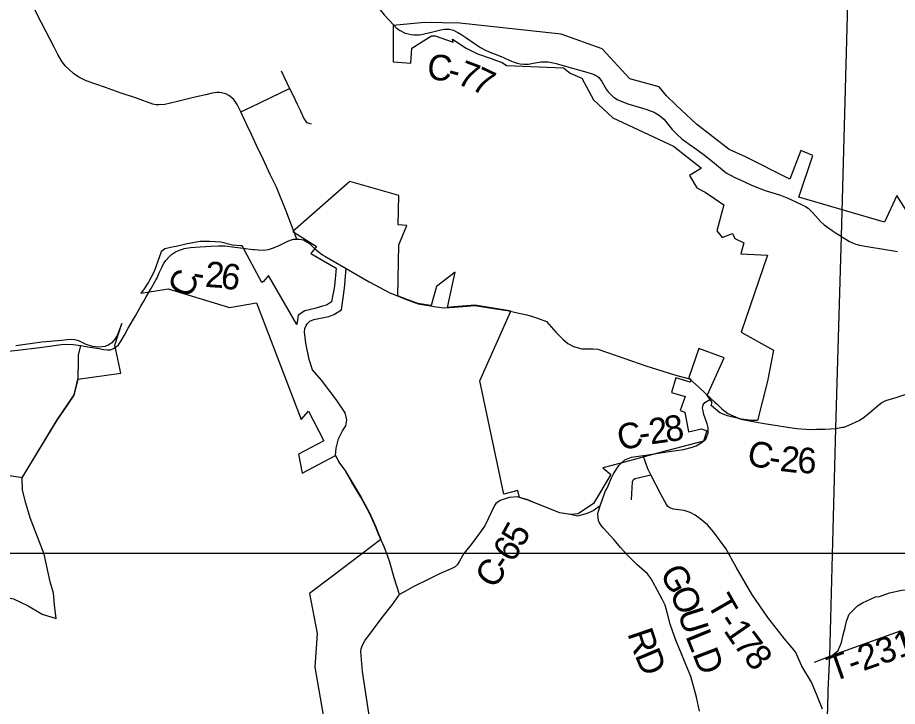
# Model space of a CAD drawing. Extents: x 2402298 to 2498138, y 789485 to 950881.
# Drawn here: x 2476688 to 2487007, y 857480 to 865555 of the extents above; entities that cross this region are included whole.
import ezdxf

# ---------------------------------------------------------------- set-up
doc = ezdxf.new("R2010")
doc.units = 0
for name, color, linetype in [('GM_X_City_Street', 7, 'Continuous'), ('GM_X_Corporation', 7, 'Continuous'), ('GM_X_County_Road', 7, 'Continuous'), ('GM_X_County_Road_Text', 7, 'Continuous'), ('GM_X_Township', 7, 'Continuous'), ('GM_X_Township_Road', 7, 'Continuous'), ('GM_X_Township_Road_Text', 7, 'Continuous'), ('SH_Text', 7, 'Continuous')]:
    doc.layers.add(name, color=color, linetype=linetype)

msp = doc.modelspace()

# ---------------------------------------------------------------- linework, layer by layer
at = {"layer": 'GM_X_City_Street'}
for points in [[(2479778, 864930), (2479879, 864725), (2479920, 864642), (2479968, 864542), (2480003, 864469), (2480011, 864451)], [(2479306, 864450), (2479433, 864509), (2479879, 864725)], [(2480011, 864451), (2480047, 864371), (2480059, 864350), (2480076, 864327), (2480132, 864309)]]:
    msp.add_lwpolyline(points, dxfattribs=at)
at = {"layer": 'GM_X_Corporation'}
for points in [[(2487193, 863169), (2487001, 863468), (2486857, 863158), (2485849, 863449), (2486015, 863937), (2485875, 863997), (2485747, 863661), (2485225, 863921), (2485034, 864008), (2484649, 864305), (2484413, 864530), (2484300, 864639), (2484214, 864743), (2483869, 864837), (2483546, 865190), (2483065, 865362), (2481873, 865488), (2481459, 865498), (2481091, 865464), (2481093, 865038), (2481299, 865020), (2481312, 865197), (2481543, 865342), (2481587, 865343), (2481795, 865267), (2481789, 865302), (2481949, 865198), (2482076, 865133), (2482083, 865132), (2482255, 865072), (2482282, 865059), (2482371, 865028), (2482423, 864992), (2483091, 864968), (2483169, 864902), (2483307, 864844), (2483441, 864590), (2483668, 864379), (2484379, 864047), (2484708, 863790), (2484570, 863704), (2484656, 863561), (2484752, 863508), (2484972, 863359), (2484890, 863055), (2484951, 862978), (2485073, 863025), (2485099, 862967), (2485205, 862913), (2485170, 862785), (2485485, 862768), (2485173, 861866), (2485554, 861655), (2485483, 861292), (2485368, 860830), (2485300, 860833), (2485174, 860846), (2485014, 860888), (2484924, 860920), (2484822, 861006), (2484836, 861045), (2484777, 861126), (2484974, 861566), (2484677, 861675), (2484560, 861334), (2484584, 861313), (2484575, 861282), (2484409, 861333), (2484359, 861160), (2484517, 861112), (2484461, 860948), (2484512, 860929), (2484557, 860700), (2484709, 860732), (2484772, 860709), (2484731, 860591), (2484224, 860455), (2483763, 860332), (2483552, 860276), (2483646, 860199), (2483443, 859859), (2483263, 859736), (2483171, 859730), (2483047, 859750), (2482764, 859861), (2482671, 859900), (2482573, 859929), (2482556, 860010), (2482391, 859966), (2482109, 861297), (2482473, 862114), (2482433, 862123), (2482051, 862183), (2481955, 862175), (2481810, 862164), (2481730, 862157), (2481820, 862569), (2481600, 862404), (2481540, 862179), (2481530, 862180), (2481384, 862203), (2481235, 862257), (2481147, 862294), (2481158, 862890), (2481254, 863117), (2481153, 863124), (2481159, 863468), (2480586, 863635), (2479916, 863049), (2480192, 862870), (2480128, 862789), (2480425, 862617), (2480403, 862407), (2480369, 862224), (2480311, 862185), (2480265, 862171), (2480174, 862144), (2480055, 862117), (2479977, 862067), (2479965, 861957), (2479630, 862532), (2479574, 862461), (2479553, 862450), (2479323, 862878), (2479306, 862878), (2479210, 862887), (2479073, 862922), (2478939, 862930), (2478831, 862929), (2478678, 862901), (2478546, 862873), (2478519, 862867), (2478414, 862845), (2478372, 862808), (2478288, 862578), (2478222, 862455), (2478163, 862364), (2478133, 862325), (2478211, 862338), (2478453, 862376), (2479175, 862155), (2479490, 862210), (2480015, 860842), (2480101, 860942), (2480278, 860595), (2479981, 860438), (2480024, 860213), (2480417, 860422), (2480465, 860333), (2480528, 860251), (2480607, 860112), (2480713, 859935), (2480816, 859748), (2480885, 859593), (2480920, 859503), (2480950, 859437), (2480380, 859007), (2480111, 858805), (2480202, 858336), (2480174, 857941), (2480300, 857222)], [(2475627, 860345), (2476742, 860163), (2476765, 860200), (2477152, 860839), (2477351, 861132), (2477396, 861315), (2477898, 861387), (2477828, 861716), (2477910, 861968), (2477854, 861829), (2477828, 861785), (2477795, 861744), (2477758, 861719), (2477715, 861701), (2477639, 861693), (2477565, 861700), (2477493, 861723), (2477407, 861764), (2477356, 861777), (2477303, 861781), (2477201, 861771), (2476971, 861751), (2476668, 861707)]]:
    msp.add_lwpolyline(points, dxfattribs=at)
at = {"layer": 'GM_X_County_Road'}
msp.add_line((2480293, 862757), (2480542, 862614), dxfattribs=at)
for points in [[(2480269, 866045), (2480346, 866031), (2480430, 866017), (2480513, 866001), (2480583, 865985), (2480637, 865965), (2480682, 865942), (2480721, 865918), (2480762, 865883), (2480794, 865845), (2480924, 865666), (2480988, 865587), (2481100, 865465), (2481132, 865433), (2481174, 865403), (2481217, 865381)], [(2479963, 862959), (2479838, 863286), (2479723, 863569), (2479652, 863717), (2479568, 863897), (2479491, 864057), (2479432, 864185), (2479377, 864299), (2479325, 864407), (2479306, 864450), (2479272, 864519), (2479257, 864547), (2479238, 864573), (2479223, 864594), (2479201, 864616), (2479165, 864641), (2479129, 864660), (2479081, 864674), (2479054, 864678), (2479023, 864677), (2478970, 864669), (2478911, 864655), (2478751, 864617), (2478548, 864568), (2478414, 864535), (2478349, 864531), (2478313, 864534), (2478273, 864542), (2478081, 864609), (2477890, 864674), (2477717, 864734), (2477492, 864815), (2477406, 864858), (2477344, 864901), (2477244, 864990), (2477202, 865049), (2477158, 865122), (2477116, 865208), (2476967, 865494), (2476851, 865723)], [(2481217, 865381), (2481221, 865378), (2481267, 865363), (2481306, 865356), (2481337, 865353), (2481369, 865353), (2481400, 865354), (2481426, 865358), (2481473, 865367), (2481528, 865381), (2481653, 865411), (2481691, 865418), (2481729, 865420), (2481755, 865418), (2481780, 865413), (2481802, 865406), (2481828, 865394), (2481853, 865381), (2481898, 865353), (2481946, 865321), (2482060, 865245), (2482119, 865206), (2482167, 865177), (2482226, 865149), (2482289, 865125), (2482340, 865106), (2482387, 865087), (2482455, 865055), (2482481, 865044)], [(2482481, 865044), (2482501, 865036), (2482546, 865022), (2482583, 865015), (2482624, 865011), (2482653, 865010), (2482681, 865011), (2482735, 865020), (2482783, 865029), (2482827, 865035), (2482880, 865037), (2482907, 865036), (2482930, 865032), (2482968, 865025), (2483003, 865017), (2483152, 864974), (2483268, 864942), (2483363, 864915), (2483427, 864896), (2483450, 864887), (2483470, 864877), (2483487, 864867), (2483504, 864854), (2483522, 864834), (2483541, 864807), (2483576, 864743), (2483593, 864716), (2483616, 864686), (2483643, 864656), (2483678, 864624), (2483693, 864613), (2483709, 864603), (2483728, 864592), (2483746, 864583), (2483794, 864562), (2483845, 864545), (2484019, 864492), (2484069, 864476), (2484119, 864459), (2484142, 864450), (2484166, 864439), (2484187, 864427), (2484206, 864415), (2484237, 864391), (2484266, 864365), (2484292, 864336), (2484320, 864301), (2484365, 864244), (2484391, 864214), (2484422, 864184), (2484478, 864134), (2484564, 864072), (2484653, 864008), (2484745, 863942), (2484859, 863854), (2484914, 863806), (2484946, 863778), (2484981, 863750), (2485012, 863729), (2485048, 863708), (2485099, 863681), (2485154, 863656), (2485297, 863592), (2485405, 863546), (2485455, 863528), (2485635, 863474), (2485714, 863441), (2485822, 863393), (2485897, 863358), (2485929, 863340), (2485959, 863320), (2486004, 863277), (2486046, 863231), (2486107, 863164), (2486147, 863127), (2486241, 863060), (2486300, 863021), (2486309, 863015), (2486348, 862991)], [(2486348, 862991), (2486352, 862988), (2486445, 862929), (2486480, 862913), (2486520, 862899), (2486562, 862888), (2486654, 862873), (2486845, 862842), (2486967, 862821), (2487008, 862811)], [(2479464, 862837), (2479510, 862832), (2479567, 862830), (2479632, 862837), (2479691, 862856), (2479762, 862886), (2479842, 862927), (2479886, 862945), (2479929, 862956), (2479963, 862959)], [(2479963, 862959), (2479994, 862958), (2480042, 862948), (2480078, 862927), (2480110, 862905), (2480172, 862849), (2480214, 862812), (2480264, 862774), (2480293, 862757)], [(2478323, 862506), (2478349, 862562), (2478378, 862625), (2478405, 862675), (2478432, 862712), (2478462, 862747), (2478495, 862778), (2478541, 862809), (2478587, 862830), (2478624, 862841)], [(2478624, 862841), (2478643, 862847), (2478716, 862858), (2478830, 862867), (2478954, 862877), (2479049, 862880), (2479118, 862878), (2479240, 862862), (2479332, 862851), (2479448, 862838), (2479464, 862837)], [(2480534, 860239), (2480529, 860248), (2480513, 860269), (2480466, 860330), (2480417, 860421), (2480426, 860508), (2480451, 860618), (2480499, 860709), (2480537, 860769), (2480548, 860838), (2480529, 860923), (2480423, 861076), (2480253, 861305), (2480147, 861426), (2480106, 861548), (2480070, 861739), (2480054, 861870), (2480057, 861912), (2480073, 861947), (2480089, 861970), (2480115, 861996), (2480162, 862017), (2480340, 862052), (2480398, 862075), (2480487, 862128), (2480523, 862382), (2480542, 862614)], [(2480542, 862614), (2480810, 862457), (2481055, 862330), (2481065, 862326), (2481192, 862272)], [(2478168, 862229), (2478193, 862273), (2478246, 862367), (2478312, 862483), (2478323, 862506)], [(2481192, 862272), (2481236, 862254), (2481385, 862200), (2481455, 862189), (2481531, 862177), (2481597, 862166)], [(2477905, 861772), (2477940, 861832), (2477983, 861913), (2478069, 862059), (2478134, 862172), (2478168, 862229)], [(2481597, 862166), (2481658, 862156), (2481689, 862151), (2481811, 862161), (2481910, 862169)], [(2481910, 862169), (2481956, 862173), (2482052, 862180), (2482373, 862130), (2482435, 862120), (2482532, 862098)], [(2482532, 862098), (2482661, 862069), (2482726, 862050), (2482785, 862033), (2482890, 861994), (2482999, 861869), (2483082, 861784), (2483142, 861736), (2483209, 861699), (2483307, 861670), (2483437, 861672), (2483495, 861669), (2483810, 861558), (2484057, 861471), (2484331, 861388), (2484447, 861351), (2484452, 861350), (2484496, 861338)], [(2476034, 861660), (2476039, 861659), (2476091, 861649), (2476176, 861635), (2476282, 861626), (2476385, 861627), (2476532, 861639), (2476654, 861653), (2476980, 861692), (2477200, 861722), (2477262, 861726), (2477340, 861721), (2477430, 861709), (2477490, 861700), (2477564, 861687), (2477643, 861674), (2477697, 861665), (2477741, 861661), (2477777, 861662), (2477812, 861676), (2477843, 861697), (2477870, 861719), (2477894, 861754), (2477905, 861772)], [(2484496, 861338), (2484570, 861319), (2484681, 861220), (2484822, 861086)], [(2486362, 860752), (2486381, 860755), (2486436, 860775), (2486559, 860831), (2486623, 860875), (2486665, 860909), (2486708, 860945), (2486791, 861014), (2486825, 861041), (2486855, 861060), (2486885, 861070), (2486979, 861098), (2487122, 861145), (2487343, 861226), (2487541, 861292), (2487648, 861333)], [(2484055, 860427), (2484225, 860453), (2484386, 860475), (2484498, 860493), (2484587, 860514), (2484647, 860536), (2484707, 860569), (2484761, 860614), (2484786, 860686), (2484787, 860746), (2484776, 860794), (2484751, 860858), (2484736, 860903), (2484728, 860945), (2484721, 860976), (2484727, 861017), (2484748, 861043), (2484822, 861086)], [(2484822, 861086), (2484865, 861048), (2484896, 861019)], [(2484896, 861019), (2484949, 860970), (2485019, 860915), (2485172, 860848), (2485314, 860821), (2485353, 860813)], [(2485353, 860813), (2485443, 860795), (2485573, 860776), (2485717, 860752), (2485827, 860736), (2485983, 860728), (2486059, 860729), (2486158, 860730), (2486284, 860739), (2486362, 860752)], [(2483679, 860208), (2483703, 860249), (2483739, 860303), (2483764, 860329), (2483812, 860370), (2483890, 860400), (2484025, 860423), (2484055, 860427)], [(2481014, 859281), (2481003, 859310), (2480989, 859349), (2480922, 859500), (2480886, 859590), (2480817, 859745), (2480715, 859932), (2480609, 860109), (2480534, 860239)], [(2483615, 860067), (2483651, 860151), (2483679, 860208)], [(2483522, 859831), (2483582, 860007), (2483603, 860039), (2483615, 860067)], [(2482692, 859890), (2482677, 859896), (2482632, 859910), (2482551, 859935), (2482454, 859927), (2482349, 859895), (2482299, 859860), (2482281, 859834), (2482169, 859598), (2482087, 859482), (2482007, 859376), (2481922, 859273), (2481889, 859217), (2481867, 859173), (2481842, 859138), (2481820, 859117), (2481774, 859092), (2481638, 859032), (2481510, 858972), (2481334, 858885), (2481166, 858792), (2481104, 858986), (2481053, 859169), (2481014, 859281)], [(2483189, 859724), (2483169, 859728), (2483118, 859737), (2483046, 859750), (2482832, 859834), (2482692, 859890)], [(2483522, 859831), (2483439, 859774), (2483358, 859739), (2483338, 859732)], [(2484687, 857422), (2484649, 857589), (2484583, 857830), (2484527, 857969), (2484467, 858115), (2484413, 858243), (2484368, 858364), (2484341, 858442), (2484308, 858580), (2484283, 858666), (2484249, 858736), (2484220, 858788), (2484195, 858840), (2484144, 858933), (2484111, 858986), (2484075, 859032), (2483952, 859145), (2483837, 859257), (2483761, 859344), (2483684, 859434), (2483637, 859484), (2483558, 859570), (2483537, 859595), (2483513, 859633), (2483500, 859661), (2483496, 859694), (2483494, 859733), (2483500, 859770), (2483522, 859831)], [(2483338, 859732), (2483288, 859717), (2483255, 859711), (2483189, 859724)]]:
    msp.add_lwpolyline(points, dxfattribs=at)
at = {"layer": 'GM_X_Township'}
msp.add_lwpolyline([(2485905, 840571), (2485987, 845862), (2486061, 849212), (2486137, 855691), (2486147, 856025), (2486179, 857085), (2486182, 857211), (2486195, 857631), (2486196, 857665), (2486214, 858070), (2486283, 860742), (2486351, 862991), (2486496, 868310), (2486601, 871155)], dxfattribs=at)
at = {"layer": 'GM_X_Township_Road'}
for points in [[(2477403, 861550), (2477404, 861599), (2477430, 861709)], [(2475162, 858563), (2476197, 858791), (2476468, 858777), (2476640, 858741), (2476811, 858659), (2476976, 858562), (2477141, 858510), (2477122, 858670), (2477110, 858808), (2477069, 858939), (2476998, 859265), (2476836, 859691), (2476786, 859862), (2476744, 860016), (2476743, 860160), (2476766, 860197), (2477153, 860836), (2477274, 861012), (2477352, 861129), (2477397, 861312), (2477403, 861550)], [(2486127, 857446), (2486065, 857602), (2486001, 857764), (2485887, 857953), (2485813, 858119), (2485682, 858271), (2485486, 858523), (2485300, 858794), (2485117, 859114), (2484994, 859332), (2484851, 859527), (2484780, 859607), (2484693, 859679), (2484634, 859723), (2484576, 859752), (2484506, 859776), (2484379, 859792), (2484337, 859806), (2484315, 859825), (2484299, 859847), (2484237, 859962), (2484114, 860196), (2484078, 860266), (2484025, 860423)], [(2483887, 859901), (2483901, 860113), (2483905, 860125)], [(2483905, 860125), (2483910, 860138), (2483933, 860151), (2484114, 860196)], [(2481460, 856257), (2481418, 856291), (2481316, 856378), (2481190, 856481), (2481084, 856580), (2481010, 856733), (2480989, 856773), (2480896, 856953), (2480818, 857324), (2480732, 857888), (2480714, 858122), (2480719, 858155), (2480731, 858191), (2480766, 858255), (2480796, 858296), (2480963, 858521), (2481085, 858675), (2481166, 858792)], [(2486035, 857998), (2486215, 858067), (2486241, 858076), (2486313, 858134), (2486353, 858230), (2486370, 858320), (2486393, 858405), (2486409, 858479), (2486440, 858560), (2486540, 858657), (2486596, 858693), (2486752, 858764), (2486796, 858770), (2486915, 858811), (2487060, 858842), (2487147, 858846), (2487259, 858838), (2487386, 858854), (2487467, 858832), (2487482, 858828), (2487508, 858813)], [(2487178, 857974), (2487072, 858342), (2487041, 858361), (2486241, 858076)]]:
    msp.add_lwpolyline(points, dxfattribs=at)
at = {"layer": 'SH_Text'}
msp.add_lwpolyline([(2448187, 889729), (2496836, 889729), (2496836, 859271), (2448187, 859271)], close=True, dxfattribs=at)

# ---------------------------------------------------------------- texts
at = {"layer": 'GM_X_County_Road_Text'}
for s, rotation, p in [('C', 354.002, (2481481, 864835)), ('7', 339.2606, (2481825, 864782)), ('7', 334.5219, (2481992, 864719)), ('-', 344.9982, (2481714, 864812)), ('2', 356.1004, (2478881, 862399)), ('C', 63.9103, (2478703, 862248)), ('6', 351.5684, (2479058, 862387)), ('-', 349.8619, (2478726, 862425)), ('2', 8.1571, (2484113, 860550)), ('8', 9.1663, (2484300, 860576)), ('C', 14.2634, (2483763, 860473)), ('-', 8.6788, (2483993, 860531)), ('C', 348.4911, (2485230, 860313)), ('2', 353.3259, (2485620, 860241)), ('6', 357.9368, (2485830, 860217)), ('-', 351.0536, (2485486, 860262)), ('5', 61.4078, (2482609, 859333)), ('6', 56.2839, (2482491, 859154)), ('C', 55.1429, (2482277, 858845)), ('-', 55.3795, (2482418, 859048)), ('G', 297.7446, (2484215, 859047)), ('O', 291.3103, (2484334, 858822)), ('U', 287.4512, (2484429, 858581)), ('R', 288.5238, (2483837, 858336)), ('L', 292.2084, (2484517, 858304)), ('D', 292.7308, (2483923, 858080)), ('D', 290.8963, (2484601, 858097))]:
    msp.add_text(s, height=300, rotation=rotation, dxfattribs=at).set_placement(p)
at = {"layer": 'GM_X_Township_Road_Text'}
for s, rotation, p in [('T', 299.8634, (2484766, 858689)), ('1', 304.7105, (2484961, 858368)), ('-', 303.8494, (2484889, 858475)), ('7', 307.217, (2485074, 858205)), ('T-231', 19.4179, (2486249, 857766)), ('8', 308.9612, (2485192, 858050))]:
    msp.add_text(s, height=300, rotation=rotation, dxfattribs=at).set_placement(p)

doc.saveas('drawing.dxf')
